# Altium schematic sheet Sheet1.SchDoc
size A4
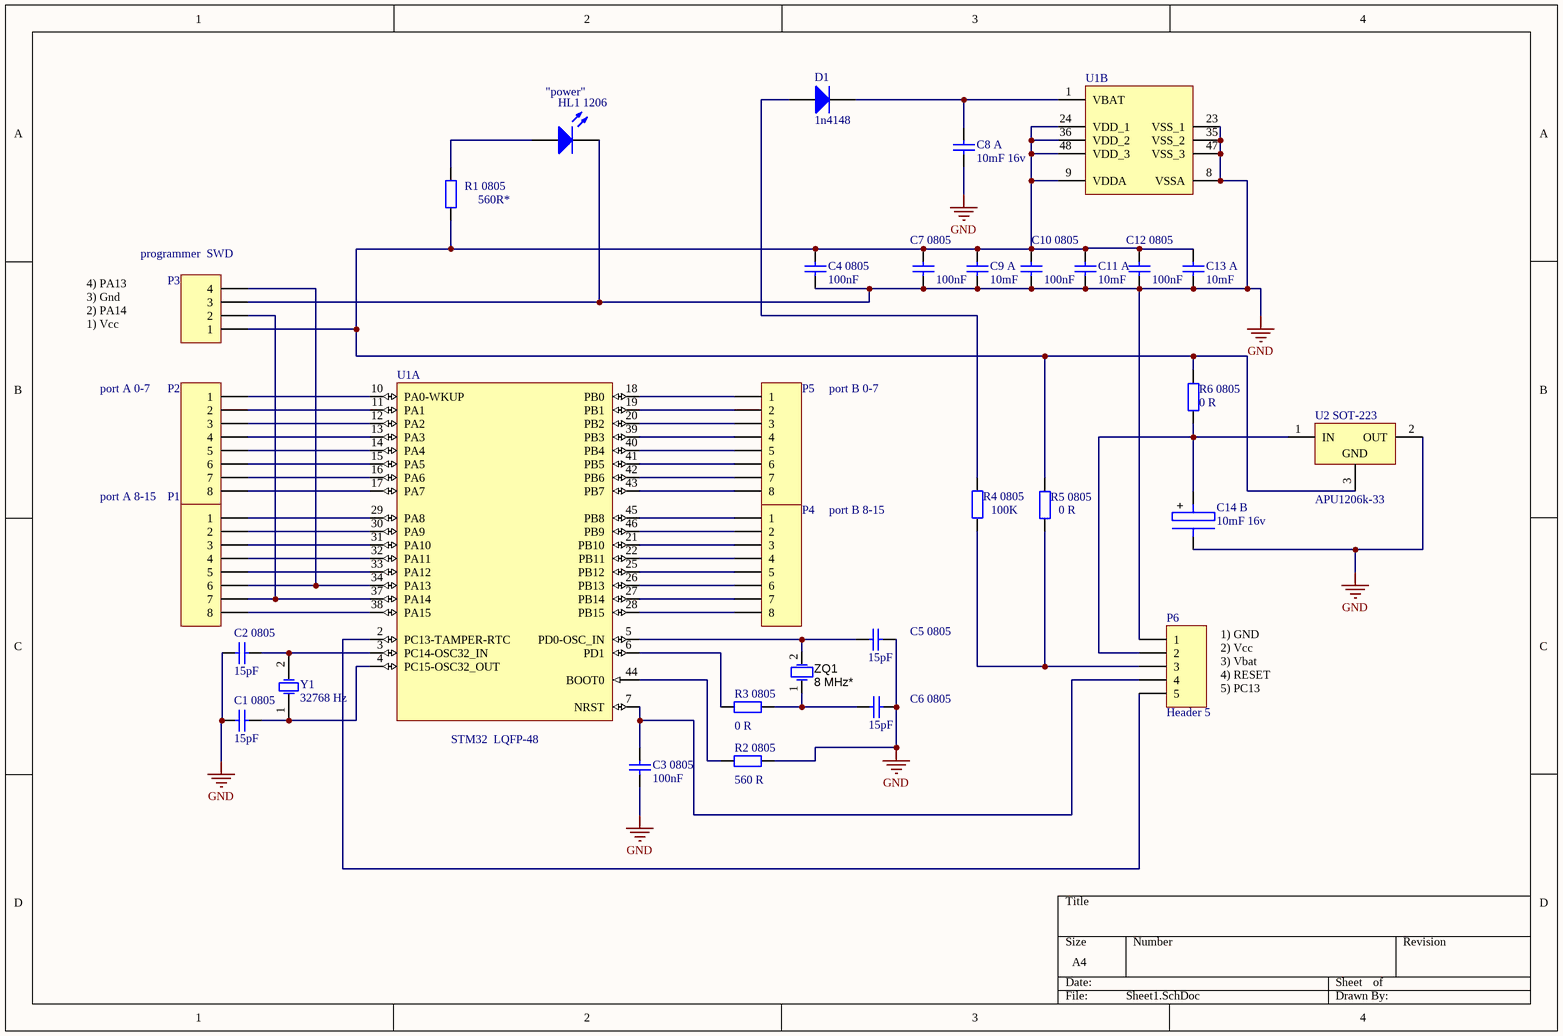
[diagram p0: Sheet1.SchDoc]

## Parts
C1_0805  value 15pF  [C0805]  (hidden comment: Cap Semi)
C2_0805  value 15pF  [C0805]  (hidden comment: Cap Semi)
C3_0805  value 100nF  [C0805 - wa]  (hidden comment: Cap Semi)
C4_0805  value 100nF  [C0805]  (hidden comment: Cap Semi)
C5_0805  value 15pF  [C0805]  (hidden comment: Cap Semi)
C6_0805  value 15pF  [C0805]  (hidden comment: Cap Semi)
C7_0805  value 100nF  [C0805]  (hidden comment: Cap Semi)
C8_A  value 10mF 16v  [C1206]  (hidden comment: Cap Semi)
C9_A  value 10mF  [C0805 - wa]  (hidden comment: Cap Semi)
C10_0805  value 100nF  [C0805]  (hidden comment: Cap Semi)
C11_A  value 10mF  [C0805 - wa]  (hidden comment: Cap Semi)
C12_0805  value 100nF  [C0805]  (hidden comment: Cap Semi)
C13_A  value 10mF  [C0805 - wa]  (hidden comment: Cap Semi)
C14_B  value 10mF 16v  [3528 - Type B]  (hidden comment: Cap polar_Vishay Type B)
D1  1n4148  [MELF]
HL1_1206  "power"  [C1206]
P1  port A 8-15  [HDR1X8]
P2  port A 0-7  [HDR1X8]
P3  programmer  SWD  [HDR1X4]
P4  port B 8-15  [HDR1X8]
P5  port B 0-7  [HDR1X8]
P6  Header 5  [HDR1X5]
R1_0805  value 560R*  [C0805]  (hidden comment: Res2)
R2_0805  value 560 R  [C0805]  (hidden comment: Res2)
R3_0805  value 0 R  [C0805]  (hidden comment: Res2)
R4_0805  value 100K  [C0805]  (hidden comment: Res2)
R5_0805  value 0 R  [C0805]
R6_0805  value 0 R  [1206 - wa]  (hidden comment: Resistor 1206)
U1  STM32  LQFP-48  [LQFP48_M]  (parts A,B of 2)
U2_SOT-223  APU1206k-33  [DPAK]
Y1  32768 Hz  [R38]
ZQ1  8 MHz*  [HC49S]

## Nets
GND: C1_0805.2 C2_0805.2 C3_0805.2 C4_0805.2 C5_0805.2 C6_0805.2 C7_0805.2 C8_A.2 C9_A.2 C10_0805.2 C11_A.2 C12_0805.1 C13_A.1 C14_B.2 HL1_1206.2(K) P3.3 P6.1 R2_0805.2 U1.8(VSSA) U1.23(VSS_1) U1.35(VSS_2) U1.47(VSS_3) U2_SOT-223.2(OUT)
NetC1_0805_1: C1_0805.1 U1.4(PC15-OSC32_OUT) Y1.1(OSC1)
NetC2_0805_1: C2_0805.1 U1.3(PC14-OSC32_IN) Y1.2(OSC2)
NetC3_0805_1: C3_0805.1 P6.4 U1.7(NRST)
NetC4_0805_1: C4_0805.1 C7_0805.1 C9_A.1 C10_0805.1 C11_A.1 C12_0805.2 C13_A.2 P3.1 R1_0805.1 R5_0805.1 R6_0805.2 U1.9(VDDA) U1.24(VDD_1) U1.36(VDD_2) U1.48(VDD_3) U2_SOT-223.3(GND)
NetC5_0805_1: C5_0805.1 U1.5(PD0-OSC_IN) ZQ1.2(OSC2)
NetC6_0805_1: C6_0805.1 R3_0805.2 ZQ1.1(OSC1)
NetC8_A_1: C8_A.1 D1.2(K) U1.1(VBAT)
NetC14_B_1: C14_B.1 P6.2 R6_0805.1 U2_SOT-223.1(IN)
NetD1_1: D1.1(A) R4_0805.2
NetHL1_1206_1: HL1_1206.1(A) R1_0805.2
NetP1_1: P1.1 U1.29(PA8)
NetP1_2: P1.2 U1.30(PA9)
NetP1_3: P1.3 U1.31(PA10)
NetP1_4: P1.4 U1.32(PA11)
NetP1_5: P1.5 U1.33(PA12)
NetP1_6: P1.6 P3.4 U1.34(PA13)
NetP1_7: P1.7 P3.2 U1.37(PA14)
NetP1_8: P1.8 U1.38(PA15)
NetP2_1: P2.1 U1.10(PA0-WKUP)
NetP2_2: P2.2 U1.11(PA1)
NetP2_3: P2.3 U1.12(PA2)
NetP2_4: P2.4 U1.13(PA3)
NetP2_5: P2.5 U1.14(PA4)
NetP2_6: P2.6 U1.15(PA5)
NetP2_7: P2.7 U1.16(PA6)
NetP2_8: P2.8 U1.17(PA7)
NetP4_1: P4.1 U1.45(PB8)
NetP4_2: P4.2 U1.46(PB9)
NetP4_3: P4.3 U1.21(PB10)
NetP4_4: P4.4 U1.22(PB11)
NetP4_5: P4.5 U1.25(PB12)
NetP4_6: P4.6 U1.26(PB13)
NetP4_7: P4.7 U1.27(PB14)
NetP4_8: P4.8 U1.28(PB15)
NetP5_1: P5.1 U1.18(PB0)
NetP5_2: P5.2 U1.19(PB1)
NetP5_3: P5.3 U1.20(PB2)
NetP5_4: P5.4 U1.39(PB3)
NetP5_5: P5.5 U1.40(PB4)
NetP5_6: P5.6 U1.41(PB5)
NetP5_7: P5.7 U1.42(PB6)
NetP5_8: P5.8 U1.43(PB7)
NetP6_3: P6.3 R4_0805.1 R5_0805.1
NetP6_5: P6.5 U1.2(PC13-TAMPER-RTC)
NetR2_0805_1: R2_0805.1 U1.44(BOOT0)
NetR3_0805_1: R3_0805.1 U1.6(PD1)

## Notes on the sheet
- 4) PA13
  3) Gnd
  2) PA14
  1) Vcc
- 1) GND
  2) Vcc
  3) Vbat
  4) RESET
  5) PC13

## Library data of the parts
C1_0805 C2_0805 C3_0805 C4_0805 C5_0805 C6_0805 C7_0805 C8_A C9_A C10_0805 C11_A C12_0805 C13_A = Cap Semi: Capacitor (Semiconductor SIM Model)
C14_B = Cap polar_Vishay Type B: Capacitor (Model Sergeev)
D1 = SM4001: Диод SMD 1A, 1000V; Разработал: Сергеев
HL1_1206 = LED CMD: Typical INFRARED GaAs LED
P1 P2 P4 P5 = Header 8: Header, 8-Pin
P3 = Header 4: Header, 4-Pin
P6 = Header 5: Header, 5-Pin
R1_0805 R2_0805 R3_0805 R4_0805 = Res2: Resistor
R5_0805 = Resistor 0805
U1 = STM32F100C8T6B: STM32 ARM-based 32-bit MCU Value Line with 64 kB Flash, 8 kB Internal RAM, Internal Code B, -40 to +85°C Temperature, 48-Pin LQFP, Tray
U2_SOT-223 = L7805ABV: Precision 1A Regulator; Note: Tab is connected to pin 3 (GND).
Y1 ZQ1 = XTAL: Crystal Oscillator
